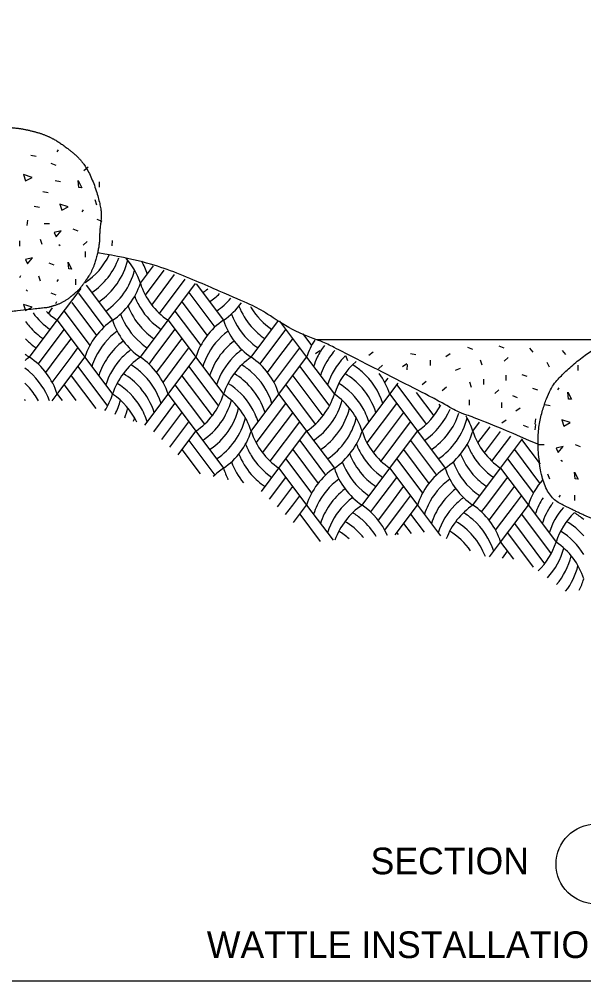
# Model space of a CAD drawing. Extents: x 99862 to 103680, y 99470 to 102076.
# Drawn here: x 101304 to 101727, y 100000 to 100721 of the extents above; entities that cross this region are included whole.
import ezdxf

# ---------------------------------------------------------------- set-up
doc = ezdxf.new("R2010")
doc.units = 0
for name, color, linetype in [('Level 1', 7, 'Continuous'), ('Level 13', 7, 'Continuous'), ('Level 2', 7, 'Continuous'), ('Level 20', 7, 'Continuous'), ('Level 3', 7, 'Continuous'), ('Level 4', 7, 'Continuous'), ('Level 5', 7, 'Continuous')]:
    doc.layers.add(name, color=color, linetype=linetype)

msp = doc.modelspace()

# ---------------------------------------------------------------- linework, layer by layer
at = {"layer": 'Level 1'}
msp.add_lwpolyline([(99862, 99999.5), (103151, 99999.5), (103151, 102075.5), (99862, 102075.5)], close=True, dxfattribs=at)
at = {"layer": 'Level 13'}
for p, q in [((101394.86, 100522.53), (101404.69, 100535.64)), ((101398.6, 100513.66), (101412.6, 100532.32)), ((101403.42, 100506.23), (101420.5, 100529)), ((101354.31, 100521.16), (101374.07, 100494.81)), ((101409.13, 100499.98), (101428.41, 100525.68)), ((101415.64, 100494.81), (101436.31, 100522.37)), ((101436.67, 100522.21), (101457.22, 100494.81)), ((101332.49, 100494.81), (101350.35, 100518.63)), ((101348.39, 100515.18), (101367.55, 100489.64)), ((101431.24, 100515.6), (101450.71, 100489.64)), ((101343.37, 100508.03), (101361.84, 100483.39)), ((101426.04, 100508.67), (101445, 100483.39)), ((101325.97, 100499.98), (101329.02, 100504.05)), ((101337.69, 100501.74), (101357.02, 100475.96)), ((101420.84, 100501.74), (101440.18, 100475.96)), ((101311.7, 100467.09), (101332.49, 100494.81)), ((101332.49, 100494.81), (101353.28, 100467.09)), ((101394.86, 100467.09), (101415.64, 100494.81)), ((101415.64, 100494.81), (101436.43, 100467.09)), ((101478.01, 100467.09), (101498.57, 100494.51)), ((101499.34, 100494.09), (101519.59, 100467.09)), ((101322.09, 100467.09), (101337.69, 100487.88)), ((101405.25, 100467.09), (101420.84, 100487.88)), ((101488.41, 100467.09), (101504, 100487.88)), ((101332.49, 100467.09), (101342.88, 100480.95)), ((101415.64, 100467.09), (101426.04, 100480.95)), ((101498.8, 100467.09), (101509.2, 100480.95)), ((101516.8, 100484.67), (101523.33, 100475.96)), ((101342.88, 100467.09), (101348.08, 100474.02)), ((101426.04, 100467.09), (101431.24, 100474.02)), ((101509.2, 100467.09), (101514.39, 100474.02)), ((101318.22, 100461.92), (101322.09, 100467.09)), ((101323.92, 100455.67), (101332.49, 100467.09)), ((101328.75, 100448.24), (101342.88, 100467.09)), ((101332.49, 100439.37), (101353.28, 100467.09)), ((101353.28, 100467.09), (101374.07, 100439.37)), ((101401.37, 100461.92), (101405.25, 100467.09)), ((101407.08, 100455.67), (101415.64, 100467.09)), ((101411.9, 100448.24), (101426.04, 100467.09)), ((101415.64, 100439.37), (101436.43, 100467.09)), ((101436.43, 100467.09), (101457.22, 100439.37)), ((101484.53, 100461.92), (101488.41, 100467.09)), ((101490.24, 100455.67), (101498.8, 100467.09)), ((101495.06, 100448.24), (101509.2, 100467.09)), ((101498.8, 100439.37), (101519.59, 100467.09)), ((101519.59, 100467.09), (101540.38, 100439.37)), ((101348.08, 100460.16), (101370.32, 100430.51)), ((101431.24, 100460.16), (101453.48, 100430.51)), ((101514.39, 100460.16), (101536.63, 100430.51)), ((101342.88, 100453.23), (101361.37, 100428.59)), ((101426.04, 100453.23), (101448.66, 100423.07)), ((101509.2, 100453.23), (101531.81, 100423.07)), ((101578.21, 100448.24), (101580.63, 100451.47)), ((101337.69, 100446.3), (101346.44, 100434.63)), ((101420.84, 100446.3), (101442.95, 100416.83)), ((101504, 100446.3), (101526.11, 100416.83)), ((101581.96, 100439.37), (101588.13, 100447.61)), ((101587.15, 100446.3), (101609.26, 100416.83)), ((101328.8, 100434.46), (101332.49, 100439.37)), ((101332.49, 100439.37), (101336.12, 100434.53)), ((101398.16, 100416.06), (101415.64, 100439.37)), ((101415.64, 100439.37), (101436.43, 100411.65)), ((101478.01, 100411.65), (101498.8, 100439.37)), ((101498.8, 100439.37), (101519.59, 100411.65)), ((101561.17, 100411.65), (101581.96, 100439.37)), ((101581.96, 100439.37), (101602.75, 100411.65)), ((101601.86, 100440.55), (101614.97, 100423.07)), ((101404.91, 100411.2), (101420.84, 100432.44)), ((101481.76, 100402.79), (101504, 100432.44)), ((101564.91, 100402.79), (101587.15, 100432.44)), ((101618.76, 100431.89), (101619.79, 100430.51)), ((101410.98, 100405.44), (101426.04, 100425.51)), ((101486.58, 100395.36), (101509.2, 100425.51)), ((101569.73, 100395.36), (101592.35, 100425.51)), ((101417.06, 100399.68), (101431.24, 100418.58)), ((101492.28, 100389.11), (101514.39, 100418.58)), ((101575.44, 100389.11), (101597.55, 100418.58)), ((101644.32, 100411.65), (101649.35, 100418.36)), ((101648.07, 100402.79), (101657.15, 100414.9)), ((101423.14, 100393.92), (101436.43, 100411.65)), ((101436.43, 100411.65), (101457.22, 100383.94)), ((101498.8, 100383.94), (101519.59, 100411.65)), ((101519.59, 100411.65), (101540.38, 100383.94)), ((101581.96, 100383.94), (101602.75, 100411.65)), ((101602.75, 100411.65), (101623.53, 100383.94)), ((101652.89, 100395.36), (101664.96, 100411.45)), ((101658.6, 100389.11), (101672.77, 100408)), ((101665.11, 100383.94), (101681.62, 100405.94)), ((101431.24, 100404.72), (101450.71, 100378.76)), ((101514.39, 100404.72), (101533.86, 100378.76)), ((101597.55, 100404.72), (101617.02, 100378.76)), ((101680.79, 100405.5), (101694.8, 100386.82)), ((101426.04, 100397.8), (101439.63, 100379.68)), ((101509.2, 100397.8), (101528.15, 100372.52)), ((101592.35, 100397.8), (101611.31, 100372.52)), ((101675.51, 100397.8), (101694.32, 100372.71)), ((101504, 100390.87), (101523.33, 100365.08)), ((101587.15, 100390.87), (101606.49, 100365.08)), ((101670.31, 100390.87), (101689.65, 100365.08)), ((101485.65, 100366.4), (101498.8, 100383.94)), ((101491.7, 100360.61), (101504, 100377.01)), ((101498.8, 100383.94), (101519.59, 100356.22)), ((101561.17, 100356.22), (101581.96, 100383.94)), ((101571.56, 100356.22), (101587.15, 100377.01)), ((101581.96, 100383.94), (101602.75, 100356.22)), ((101644.32, 100356.22), (101665.11, 100383.94)), ((101654.72, 100356.22), (101670.31, 100377.01)), ((101665.11, 100383.94), (101685.9, 100356.22)), ((101498.8, 100356.22), (101509.2, 100370.08)), ((101581.96, 100356.22), (101592.35, 100370.08)), ((101665.11, 100356.22), (101675.51, 100370.08)), ((101509.2, 100356.22), (101514.39, 100363.15)), ((101592.35, 100356.22), (101597.55, 100363.15)), ((101675.51, 100356.22), (101680.7, 100363.15)), ((101497.75, 100354.82), (101498.8, 100356.22)), ((101503.8, 100349.03), (101509.2, 100356.22)), ((101509.85, 100343.23), (101519.59, 100356.22)), ((101519.59, 100356.22), (101539.42, 100329.78)), ((101567.68, 100351.05), (101571.56, 100356.22)), ((101573.39, 100344.8), (101581.96, 100356.22)), ((101578.21, 100337.37), (101592.35, 100356.22)), ((101585.99, 100333.88), (101602.75, 100356.22)), ((101602.75, 100356.22), (101620.1, 100333.08)), ((101650.84, 100351.05), (101654.72, 100356.22)), ((101656.55, 100344.8), (101665.11, 100356.22)), ((101661.37, 100337.37), (101675.51, 100356.22)), ((101665.11, 100328.5), (101685.9, 100356.22)), ((101685.9, 100356.22), (101706.69, 100328.5)), ((101514.39, 100349.29), (101529.67, 100328.92)), ((101597.55, 100349.29), (101607.68, 100335.78)), ((101680.7, 100349.29), (101702.95, 100319.63)), ((101592.35, 100342.36), (101597.92, 100334.93)), ((101675.51, 100342.36), (101698.13, 100312.2)), ((101587.15, 100335.43), (101588.17, 100334.07)), ((101670.31, 100335.43), (101689.63, 100309.67)), ((101656.7, 100317.28), (101665.11, 100328.5)), ((101665.11, 100328.5), (101674.76, 100315.64)), ((101666.43, 100316.39), (101670.31, 100321.57))]:
    msp.add_line(p, q, dxfattribs=at)
for centre, start, end in [((101324.1, 100566.67), 303.90361, 334.27617), ((101329.13, 100559.26), 303.90361, 340.27107), ((101334.33, 100552.33), 303.90361, 346.31988), ((101344.72, 100506.58), 17.6434, 41.65518), ((101349.92, 100513.51), 17.6434, 29.16926), ((101339.52, 100545.4), 303.90361, 345.77133), ((101344.72, 100538.47), 303.90361, 342.3566), ((101444.99, 100538.47), 197.64354, 236.09639), ((101412.29, 100559.26), 303.90361, 309.19679), ((101417.48, 100552.33), 303.90361, 314.47532), ((101439.79, 100531.54), 200.87781, 211.33197), ((101422.68, 100545.4), 303.90361, 319.55675), ((101427.88, 100538.47), 303.90361, 324.49811), ((101356.64, 100531.54), 216.48248, 236.09639), ((101361.83, 100538.47), 224.77759, 236.09639), ((101434.6, 100524.61), 201.43438, 220.94161), ((101439.79, 100531.54), 211.33188, 236.09639), ((101517.75, 100524.61), 201.43438, 220.94161), ((101522.95, 100531.54), 210.20479, 211.33197), ((101522.95, 100531.54), 211.33188, 236.09639), ((101351.44, 100524.61), 215.88757, 220.94161), ((101403.41, 100451.15), 123.90361, 162.3566), ((101424.2, 100510.76), 197.6434, 236.09639), ((101429.4, 100517.69), 200.24322, 228.95992), ((101486.57, 100451.15), 123.90361, 162.3566), ((101507.36, 100510.76), 197.6434, 236.09639), ((101512.55, 100517.69), 200.24322, 228.95992), ((101351.44, 100524.61), 220.94154, 236.09639), ((101408.61, 100444.22), 126.30625, 154.2266), ((101434.6, 100524.61), 220.94154, 236.09639), ((101491.76, 100444.22), 126.30625, 154.2266), ((101517.75, 100524.61), 220.94154, 236.09639), ((101346.24, 100517.69), 224.36034, 228.95992), ((101346.24, 100517.69), 228.95986, 236.09639), ((101413.81, 100437.29), 127.1006, 145.49109), ((101429.4, 100517.69), 228.95986, 236.09639), ((101496.96, 100437.29), 127.1006, 145.49109), ((101512.55, 100517.69), 228.95986, 236.09639), ((101569.72, 100451.15), 146.88602, 162.3566), ((101419, 100430.36), 126.331, 135.71278), ((101502.16, 100430.36), 126.331, 135.71278), ((101574.92, 100444.22), 142.87391, 154.2266), ((101580.12, 100437.29), 138.65698, 145.49109), ((101341.04, 100423.43), 123.90361, 128.3656), ((101341.04, 100510.76), 231.73135, 236.09639), ((101282.36, 100423.43), 17.6434, 56.09634), ((101408.61, 100444.22), 154.22654, 162.3566), ((101413.81, 100437.29), 145.49102, 162.3566), ((101419, 100430.36), 135.71269, 162.3566), ((101424.2, 100423.43), 123.90361, 162.3566), ((101365.51, 100423.43), 17.6434, 56.09634), ((101491.76, 100444.22), 154.22654, 162.3566), ((101496.96, 100437.29), 145.49102, 162.3566), ((101502.16, 100430.36), 135.71269, 162.3566), ((101507.36, 100423.43), 123.90361, 162.3566), ((101448.67, 100423.43), 17.6434, 56.09634), ((101574.92, 100444.22), 154.22654, 162.3566), ((101580.12, 100437.29), 145.49102, 162.3566), ((101585.32, 100430.36), 135.71269, 162.3566), ((101590.51, 100423.43), 129.95301, 162.3566), ((101585.32, 100430.36), 134.36024, 135.71278), ((101277.16, 100416.5), 48.95968, 53.69377), ((101360.31, 100416.5), 48.95968, 58.54646), ((101443.47, 100416.5), 48.95968, 58.54646), ((101526.63, 100416.5), 48.95968, 58.54646), ((101277.16, 100416.5), 19.93603, 48.95975), ((101355.12, 100409.57), 40.94134, 59.30215), ((101360.31, 100416.5), 17.6434, 48.95975), ((101438.27, 100409.57), 40.94134, 59.30215), ((101443.47, 100416.5), 17.6434, 48.95975), ((101521.43, 100409.57), 40.94134, 59.30215), ((101526.63, 100416.5), 17.6434, 48.95975), ((101531.82, 100423.43), 17.6434, 36.7138), ((101271.96, 100409.57), 40.94134, 46.54413), ((101271.96, 100409.57), 28.11033, 40.94141), ((101349.92, 100402.64), 31.33163, 58.48737), ((101355.12, 100409.57), 17.6434, 40.94141), ((101433.08, 100402.64), 31.33163, 58.48737), ((101438.27, 100409.57), 17.6434, 40.94141), ((101516.23, 100402.64), 31.33163, 58.48737), ((101521.43, 100409.57), 17.6434, 40.94141), ((101266.76, 100402.64), 36.95087, 38.31677), ((101323.93, 100455.32), 327.49346, 342.3566), ((101344.72, 100395.71), 25.41172, 56.09639), ((101329.13, 100448.39), 332.86799, 345.01126), ((101407.09, 100455.32), 303.90361, 342.3566), ((101412.29, 100448.39), 303.90361, 345.01126), ((101427.88, 100395.71), 17.6434, 56.09639), ((101490.24, 100455.32), 303.90361, 342.3566), ((101495.44, 100448.39), 303.90361, 345.01126), ((101511.03, 100395.71), 17.6434, 56.09639), ((101334.33, 100441.46), 337.95987, 346.31988), ((101349.92, 100402.64), 17.6434, 31.33172), ((101417.48, 100441.46), 303.90361, 346.31988), ((101433.08, 100402.64), 17.6434, 31.33172), ((101500.64, 100441.46), 303.90361, 346.31988), ((101516.23, 100402.64), 17.6434, 31.33172), ((101573.4, 100455.32), 303.90361, 332.77963), ((101578.6, 100448.39), 303.90361, 337.39439), ((101339.52, 100434.53), 343.04009, 345.77133), ((101422.68, 100434.53), 303.90361, 345.77133), ((101505.84, 100434.53), 303.90361, 345.77133), ((101583.8, 100441.46), 303.90361, 342.01731), ((101588.99, 100434.53), 303.90361, 345.77133), ((101594.19, 100395.71), 17.6434, 31.00365), ((101427.88, 100427.6), 303.90361, 342.3566), ((101528.15, 100427.6), 197.64354, 236.09639), ((101511.03, 100427.6), 303.90361, 342.3566), ((101611.3, 100427.6), 197.64354, 236.09639), ((101594.19, 100427.6), 303.90361, 342.3566), ((101694.46, 100427.6), 197.64354, 236.09639), ((101522.95, 100420.67), 200.87781, 211.33197), ((101606.1, 100420.67), 200.87781, 211.33197), ((101689.26, 100420.67), 200.87781, 211.33197), ((101517.75, 100413.74), 201.43438, 220.94161), ((101522.95, 100420.67), 211.33188, 236.09639), ((101600.91, 100413.74), 201.43438, 220.94161), ((101606.1, 100420.67), 211.33188, 236.09639), ((101684.06, 100413.74), 201.43438, 220.94161), ((101689.26, 100420.67), 211.33188, 236.09639), ((101512.55, 100406.81), 200.24322, 219.99036), ((101595.71, 100406.81), 200.24322, 228.95992), ((101678.87, 100406.81), 200.24322, 228.95992), ((101486.57, 100340.27), 123.90361, 134.72842), ((101507.36, 100399.88), 197.6434, 207.80695), ((101517.75, 100413.74), 220.94154, 236.09639), ((101569.72, 100340.27), 123.90361, 162.3566), ((101590.51, 100399.88), 197.6434, 236.09639), ((101600.91, 100413.74), 220.94154, 236.09639), ((101652.88, 100340.27), 123.90361, 162.3566), ((101673.67, 100399.88), 197.6434, 236.09639), ((101684.06, 100413.74), 220.94154, 236.09639), ((101491.76, 100333.34), 126.30625, 126.81576), ((101574.92, 100333.34), 126.30625, 154.2266), ((101658.08, 100333.34), 126.30625, 154.2266), ((101736.04, 100340.27), 138.13252, 162.3566), ((101580.12, 100326.41), 127.1006, 145.49109), ((101595.71, 100406.81), 228.95986, 236.09639), ((101663.27, 100326.41), 127.1006, 145.49109), ((101678.87, 100406.81), 228.95986, 236.09639), ((101574.92, 100333.34), 154.22654, 162.3566), ((101580.12, 100326.41), 145.49102, 162.3566), ((101585.32, 100319.48), 135.71269, 162.3566), ((101590.51, 100312.55), 123.90361, 160.74002), ((101585.32, 100319.48), 126.331, 135.71278), ((101531.82, 100312.55), 23.3003, 56.09634), ((101658.08, 100333.34), 154.22654, 162.3566), ((101663.27, 100326.41), 145.49102, 162.3566), ((101668.47, 100319.48), 135.71269, 162.3566), ((101673.67, 100312.55), 123.90361, 159.54596), ((101668.47, 100319.48), 126.331, 135.71278), ((101614.98, 100312.55), 17.6434, 56.09634), ((101741.23, 100333.34), 154.22654, 162.3566), ((101741.23, 100333.34), 147.34243, 154.2266), ((101746.43, 100326.41), 145.49102, 162.3566), ((101746.43, 100326.41), 142.92549, 145.49109), ((101526.63, 100305.62), 48.95968, 58.54646), ((101609.78, 100305.62), 48.95968, 58.54646), ((101751.63, 100319.48), 138.43819, 162.3566), ((101756.82, 100312.55), 133.84791, 162.3566), ((101692.94, 100305.62), 48.95968, 58.42509), ((101521.43, 100298.69), 40.94134, 59.30215), ((101526.63, 100305.62), 30.88287, 48.95975), ((101604.58, 100298.69), 40.94134, 59.30215), ((101609.78, 100305.62), 17.6434, 48.95975), ((101687.74, 100298.69), 40.94134, 59.30215), ((101516.23, 100291.76), 47.96656, 58.48737), ((101599.39, 100291.76), 34.87995, 58.48737), ((101682.54, 100291.76), 31.33163, 58.48737), ((101521.43, 100298.69), 38.99071, 40.94141), ((101604.58, 100298.69), 21.00561, 40.94141), ((101656.56, 100344.44), 314.40759, 342.3566), ((101677.35, 100284.84), 17.6434, 56.09639), ((101661.75, 100337.51), 317.069, 345.01126), ((101666.95, 100330.58), 319.71737, 346.31988), ((101672.15, 100323.66), 322.4567, 345.77133), ((101677.35, 100316.73), 332.40832, 342.3566)]:
    msp.add_arc(centre, 52.61, start, end, dxfattribs=at)
msp.add_open_spline([(101692.93, 100401.77), (101655.15, 100418.49), (101636.67, 100424.44), (101627.43, 100428.96), (101621.53, 100433.09), (101552.22, 100468.16), (101537.47, 100475.81), (101531.34, 100478.79), (101508.32, 100487.09), (101489.04, 100500.6), (101478.99, 100506.02), (101457.08, 100515.29), (101416.8, 100533.11), (101392.58, 100540.26), (101362.84, 100545.45)], degree=3, dxfattribs=at)
at = {"layer": 'Level 2'}
for p, q in [((101333.12, 100622.67), (101332.27, 100621.2)), ((101333.12, 100622.67), (101332.27, 100621.2)), ((101312.62, 100618.64), (101316.6, 100617.91)), ((101312.62, 100618.64), (101316.6, 100617.91)), ((101327.62, 100612.62), (101331.38, 100611.11)), ((101327.62, 100612.62), (101331.38, 100611.11)), ((101352.57, 100607.12), (101355.64, 100609.75)), ((101352.57, 100607.12), (101355.64, 100609.75)), ((101331, 100599.6), (101334.99, 100598.88)), ((101331, 100599.6), (101334.99, 100598.88)), ((101364.02, 100598.71), (101364.02, 100594.66)), ((101364.02, 100598.71), (101364.02, 100594.66)), ((101321.71, 100591.39), (101325.7, 100590.66)), ((101321.71, 100591.39), (101325.7, 100590.66)), ((101315.22, 100580.35), (101319.2, 100579.63)), ((101315.22, 100580.35), (101319.2, 100579.63)), ((101362.21, 100581.22), (101360.85, 100585.03)), ((101362.21, 100581.22), (101360.85, 100585.03)), ((101351.9, 100577.7), (101351.05, 100576.22)), ((101351.9, 100577.7), (101351.05, 100576.22)), ((101310.27, 100569.84), (101309.77, 100565.82)), ((101310.27, 100569.84), (101309.77, 100565.82)), ((101322.71, 100567.27), (101326.76, 100567.27)), ((101322.71, 100567.27), (101326.76, 100567.27)), ((101362.09, 100570.52), (101365.9, 100569.15)), ((101362.09, 100570.52), (101365.9, 100569.15)), ((101344.31, 100563.33), (101348.07, 100561.83)), ((101344.31, 100563.33), (101348.07, 100561.83)), ((101304.28, 100554.3), (101304.28, 100550.25)), ((101304.28, 100554.3), (101304.28, 100550.25)), ((101321.31, 100551.59), (101319.95, 100555.41)), ((101321.31, 100551.59), (101319.95, 100555.41)), ((101333.75, 100551.72), (101334.81, 100550.88)), ((101333.75, 100551.72), (101334.81, 100550.88)), ((101351.99, 100551.23), (101354.95, 100553.98)), ((101351.99, 100551.23), (101354.95, 100553.98)), ((101373.8, 100554.55), (101373.41, 100550.52)), ((101373.8, 100554.55), (101373.41, 100550.52)), ((101353.44, 100546.29), (101353.44, 100542.24)), ((101353.44, 100546.29), (101353.44, 100542.24)), ((101326.19, 100537.88), (101329.95, 100536.37)), ((101326.19, 100537.88), (101329.95, 100536.37)), ((101305, 100528.07), (101304.15, 100526.59)), ((101305, 100528.07), (101304.15, 100526.59)), ((101319.95, 100524.05), (101318.59, 100527.86)), ((101319.95, 100524.05), (101318.59, 100527.86)), ((101333.12, 100525.33), (101332.27, 100523.85)), ((101333.12, 100525.33), (101332.27, 100523.85)), ((101346.32, 100525.52), (101346.32, 100521.47)), ((101346.32, 100525.52), (101346.32, 100521.47)), ((101309.22, 100517.51), (101310.27, 100516.67)), ((101309.22, 100517.51), (101310.27, 100516.67)), ((101327.62, 100515.27), (101331.38, 100513.77)), ((101327.62, 100515.27), (101331.38, 100513.77)), ((101332.06, 100508.65), (101331.22, 100507.17)), ((101332.06, 100508.65), (101331.22, 100507.17)), ((101722.92, 100461.07), (101722.92, 100457.02)), ((101722.92, 100461.07), (101722.92, 100457.02)), ((101708.66, 100444.2), (101707.82, 100442.72)), ((101708.66, 100444.2), (101707.82, 100442.72)), ((101698.31, 100431.67), (101702.3, 100430.94)), ((101698.31, 100431.67), (101702.3, 100430.94)), ((101691.23, 100420.82), (101690.73, 100416.8)), ((101691.23, 100416.54), (101690.73, 100412.52)), ((101693.66, 100401.66), (101697.71, 100401.66)), ((101693.66, 100401.66), (101697.71, 100401.66)), ((101720.91, 100401.53), (101724.67, 100400.03)), ((101720.91, 100401.53), (101724.67, 100400.03)), ((101710.35, 100389.92), (101711.41, 100389.08)), ((101710.35, 100389.92), (101711.41, 100389.08)), ((101701.96, 100375.54), (101700.6, 100379.36)), ((101701.96, 100375.54), (101700.6, 100379.36)), ((101709.72, 100363.53), (101708.87, 100362.05)), ((101709.72, 100363.53), (101708.87, 100362.05)), ((101720.44, 100363.72), (101720.44, 100359.67)), ((101720.44, 100363.72), (101720.44, 100359.67))]:
    msp.add_line(p, q, dxfattribs=at)
for points in [[(101307.32, 100604.09), (101308.8, 100599.45), (101313.65, 100601.98)], [(101307.32, 100604.09), (101308.8, 100599.45), (101313.65, 100601.98)], [(101348.33, 100599.5), (101350.87, 100594.22), (101348.76, 100594.44)], [(101348.33, 100599.5), (101350.87, 100594.22), (101348.76, 100594.44)], [(101334.38, 100581.92), (101335.86, 100577.28), (101340.71, 100579.81)], [(101334.38, 100581.92), (101335.86, 100577.28), (101340.71, 100579.81)], [(101330.16, 100560.59), (101331.64, 100557.42), (101335.44, 100561.86)], [(101330.16, 100560.59), (101331.64, 100557.42), (101335.44, 100561.86)], [(101308.61, 100540.41), (101310.09, 100537.24), (101313.89, 100541.68)], [(101308.61, 100540.41), (101310.09, 100537.24), (101313.89, 100541.68)], [(101340.71, 100538.42), (101343.25, 100533.14), (101341.14, 100533.35)], [(101340.71, 100538.42), (101343.25, 100533.14), (101341.14, 100533.35)], [(101307.32, 100506.75), (101308.8, 100502.1), (101313.65, 100504.63)], [(101307.32, 100506.75), (101308.8, 100502.1), (101313.65, 100504.63)], [(101715.63, 100440.82), (101718.16, 100435.54), (101716.05, 100435.75)], [(101715.63, 100440.82), (101718.16, 100435.54), (101716.05, 100435.75)], [(101710.98, 100420.13), (101712.46, 100415.48), (101717.31, 100418.02)], [(101710.98, 100420.13), (101712.46, 100415.48), (101717.31, 100418.02)], [(101706.76, 100398.79), (101708.24, 100395.62), (101712.04, 100400.06)], [(101706.76, 100398.79), (101708.24, 100395.62), (101712.04, 100400.06)], [(101720.64, 100380.9), (101723.18, 100375.62), (101721.07, 100375.83)], [(101720.64, 100380.9), (101723.18, 100375.62), (101721.07, 100375.83)]]:
    msp.add_lwpolyline(points, close=True, dxfattribs=at)
at = {"layer": 'Level 20'}
msp.add_circle((101736.7, 100086.98), 30, dxfattribs=at)
msp.add_circle((101736.7, 100086.98), 30, dxfattribs=at)
at = {"layer": 'Level 3'}
for q in [(101527.54, 100480.15), (101531.8, 100480.15)]:
    msp.add_line((101764.98, 100480.15), q, dxfattribs=at)
at = {"layer": 'Level 4'}
for points in [[(101292.33, 100500.68), (101322.13, 100504.07), (101324.97, 100504.07), (101336.73, 100507.81), (101347.4, 100516.14), (101352.28, 100522.02), (101359.96, 100533.77), (101364.26, 100551.31), (101364.26, 100562.2), (101366.48, 100577.97), (101355.16, 100611.34), (101335.4, 100627.78), (101323.21, 100634.1), (101310.41, 100637.63), (101299.21, 100639.43), (101286.48, 100639.33), (101272.34, 100637.39), (101257.15, 100632.88), (101234.93, 100614.57), (101224.06, 100601.57), (101214.4, 100560.71), (101223.06, 100526.72), (101244.15, 100511.05), (101262.81, 100502.65), (101292.33, 100500.68), (101292.33, 100500.68)], [(101769.22, 100341.21), (101799.01, 100344.6), (101801.85, 100344.6), (101813.62, 100348.34), (101822.44, 100352.65), (101829.16, 100360.79), (101838.73, 100374.3), (101841.15, 100391.85), (101841.15, 100402.73), (101843.37, 100418.5), (101832.05, 100451.88), (101812.29, 100468.32), (101800.09, 100474.64), (101791.04, 100478.16), (101778.21, 100481), (101772.21, 100481.37), (101750.99, 100479.1), (101734.03, 100473.42), (101711.81, 100455.11), (101700.95, 100442.11), (101691.23, 100409.12), (101697.67, 100363.6), (101721.04, 100351.59), (101739.7, 100343.19), (101769.22, 100341.21), (101769.22, 100341.21)]]:
    msp.add_open_spline(points, degree=2, dxfattribs=at)
at = {"layer": 'Level 5'}
for p, q in [((101529.41, 100472), (101526.13, 100469.7)), ((101529.41, 100472), (101526.13, 100469.7)), ((101566.37, 100468.59), (101569.4, 100471.19)), ((101566.37, 100468.59), (101569.4, 100471.19)), ((101640.35, 100474.74), (101644.07, 100473.25)), ((101640.35, 100474.74), (101644.07, 100473.25)), ((101663.74, 100475.57), (101667.45, 100474.08)), ((101663.74, 100475.57), (101667.45, 100474.08)), ((101686.7, 100473.87), (101689.32, 100470.85)), ((101686.7, 100473.87), (101689.32, 100470.85)), ((101711.23, 100472.22), (101713.85, 100469.19)), ((101711.23, 100472.22), (101713.85, 100469.19)), ((101550.38, 100464.32), (101549.04, 100468.09)), ((101550.38, 100464.32), (101549.04, 100468.09)), ((101597.52, 100469.9), (101601.45, 100469.18)), ((101597.52, 100469.9), (101601.45, 100469.18)), ((101612.17, 100464.82), (101612.17, 100460.82)), ((101612.17, 100464.82), (101612.17, 100460.82)), ((101627.19, 100469.67), (101623.91, 100467.38)), ((101627.19, 100469.67), (101623.91, 100467.38)), ((101651.28, 100461.01), (101649.94, 100464.77)), ((101651.28, 100461.01), (101649.94, 100464.77)), ((101667.7, 100464.13), (101670.64, 100466.86)), ((101667.7, 100464.13), (101670.64, 100466.86)), ((101573.55, 100458.43), (101576.48, 100461.15)), ((101573.55, 100458.43), (101576.48, 100461.15)), ((101594.83, 100462.11), (101591.55, 100459.82)), ((101595.09, 100461.71), (101594.71, 100457.73)), ((101595.09, 100461.71), (101594.71, 100457.73)), ((101631.31, 100457.42), (101635, 100458.96)), ((101631.31, 100457.42), (101635, 100458.96)), ((101699.68, 100463.29), (101701.64, 100459.8)), ((101699.68, 100463.29), (101701.64, 100459.8)), ((101606.24, 100446.65), (101609.27, 100449.25)), ((101606.24, 100446.65), (101609.27, 100449.25)), ((101652.26, 100450.74), (101652.26, 100446.74)), ((101652.26, 100450.74), (101652.26, 100446.74)), ((101669.12, 100453.56), (101669.12, 100449.56)), ((101669.12, 100453.56), (101669.12, 100449.56)), ((101681.05, 100454.25), (101684.76, 100452.76)), ((101681.05, 100454.25), (101684.76, 100452.76)), ((101621.36, 100442.22), (101624.4, 100444.83)), ((101621.36, 100442.22), (101624.4, 100444.83)), ((101643.36, 100444.51), (101642.02, 100448.28)), ((101643.36, 100444.51), (101642.02, 100448.28)), ((101660.84, 100440.01), (101663.88, 100442.61)), ((101660.84, 100440.01), (101663.88, 100442.61)), ((101689.1, 100444.01), (101692.82, 100442.52)), ((101641.41, 100435.12), (101641.41, 100431.12)), ((101641.41, 100435.12), (101641.41, 100431.12)), ((101673.9, 100438.42), (101677.61, 100436.93)), ((101665.72, 100433.04), (101665.72, 100429.04)), ((101665.72, 100433.04), (101665.72, 100429.04)), ((101679.85, 100428.82), (101676.57, 100426.52)), ((101669.19, 100419.84), (101665.91, 100417.55)), ((101681.93, 100416.19), (101685.65, 100414.71))]:
    msp.add_line(p, q, dxfattribs=at)

# ---------------------------------------------------------------- texts
at = {"layer": 'Level 20'}
for s, p in [('SECTION', (101567.51, 100079.36)), ('SECTION', (101567.51, 100079.36)), ('WATTLE INSTALLATION ON SLOPES', (101444.72, 100016.53))]:
    msp.add_text(s, height=20, dxfattribs=at).set_placement(p)

doc.saveas('drawing.dxf')
